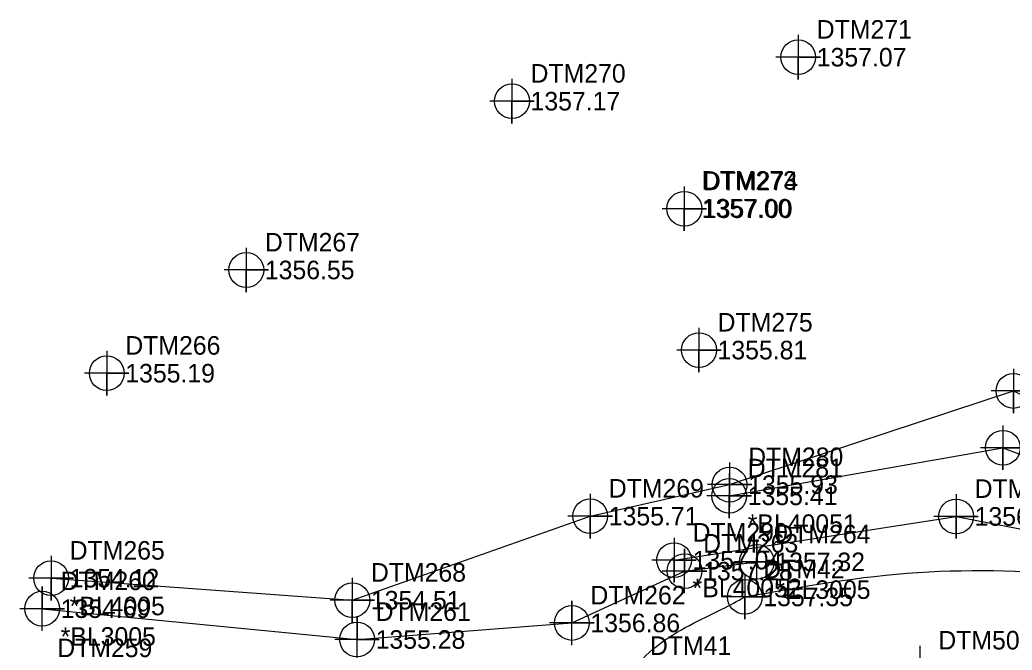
# Model space of a CAD drawing. Extents: x 1251905 to 1252853, y 859795 to 860170.
# Drawn here: x 1251953.9 to 1252087.6, y 860085.2 to 860170.2 of the extents above; entities that cross this region are included whole.
import ezdxf

# ---------------------------------------------------------------- set-up
doc = ezdxf.new("R2010")
doc.units = 0
for name, color, linetype in [('Exist DTM Breakline', 7, 'Continuous'), ('Exist DTM Breakline Cogo Comment', 7, 'Continuous'), ('Exist DTM Breakline Cogo Elevation', 7, 'Continuous'), ('Exist DTM Breakline Cogo Number', 7, 'Continuous'), ('Exist DTM Breakline Cogo Point CELL', 7, 'Continuous'), ('Exist DTM Crownline Cogo Number', 7, 'Continuous'), ('Exist DTM Crownline Cogo Point CELL', 7, 'Continuous'), ('Exist DTM Regular Point CELL', 7, 'Continuous'), ('Exist DTM Regular Point Cogo Elevation', 7, 'Continuous'), ('Exist DTM Regular Point Cogo Number', 7, 'Continuous'), ('Exist Roads EOP', 7, 'Continuous'), ('Exist Roads EOP Cogo Elevation', 7, 'Continuous'), ('Exist Roads EOP Cogo Number', 7, 'Continuous'), ('Exist Roads EOP Cogo Point CELL', 7, 'Continuous'), ('Exist Roads Soil', 7, 'Continuous'), ('Exist Roads Soil Cogo Comment', 7, 'Continuous'), ('Exist Roads Soil Cogo Elevation', 7, 'Continuous'), ('Exist Roads Soil Cogo Number', 7, 'Continuous'), ('Exist Roads Soil Cogo Point CELL', 7, 'Continuous'), ('Exist Vegetation Tree Cogo Elevation', 7, 'Continuous'), ('Exist Vegetation Tree Cogo Number', 7, 'Continuous')]:
    doc.layers.add(name, color=color, linetype=linetype)

msp = doc.modelspace()

# ---------------------------------------------------------------- linework, layer by layer
at = {"layer": 'Exist DTM Breakline'}
for points in [[(1251958.13, 860094.898), (1251998.718, 860091.928), (1252030.771, 860103.262), (1252049.551, 860107.507), (1252087.792, 860120.138), (1252107.828, 860109.909), (1252152.49, 860100.596), (1252183.064, 860094.812), (1252211.515, 860083.799), (1252212.351, 860093.22), (1252191.02, 860107.945), (1252193.563, 860139.71)], [(1252049.493, 860105.996), (1252086.378, 860112.482), (1252107.399, 860104.568), (1252151.324, 860093.395), (1252178.994, 860086.087), (1252207.96, 860079.566), (1252223.738, 860077.321)], [(1252042.065, 860097.328), (1252080.061, 860103.224), (1252106.299, 860098.116), (1252149.813, 860090.533), (1252176.834, 860084.313), (1252221.078, 860071.872)]]:
    msp.add_lwpolyline(points, dxfattribs=at)
at = {"layer": 'Exist DTM Breakline Cogo Point CELL'}
for points in [[(1252087.792, 860123.138), (1252087.792, 860117.138), (1252087.792, 860120.138), (1252090.792, 860120.138), (1252084.792, 860120.138)], [(1252086.378, 860115.482), (1252086.378, 860109.482), (1252086.378, 860112.482), (1252089.378, 860112.482), (1252083.378, 860112.482)], [(1252049.551, 860110.507), (1252049.551, 860104.507), (1252049.551, 860107.507), (1252052.551, 860107.507), (1252046.551, 860107.507)], [(1252049.493, 860108.996), (1252049.493, 860102.996), (1252049.493, 860105.996), (1252052.493, 860105.996), (1252046.493, 860105.996)], [(1252030.771, 860106.262), (1252030.771, 860100.262), (1252030.771, 860103.262), (1252033.771, 860103.262), (1252027.771, 860103.262)], [(1252080.061, 860106.224), (1252080.061, 860100.224), (1252080.061, 860103.224), (1252083.061, 860103.224), (1252077.061, 860103.224)], [(1252042.065, 860100.328), (1252042.065, 860094.328), (1252042.065, 860097.328), (1252045.065, 860097.328), (1252039.065, 860097.328)], [(1251958.13, 860097.898), (1251958.13, 860091.898), (1251958.13, 860094.898), (1251961.13, 860094.898), (1251955.13, 860094.898)], [(1251998.718, 860094.928), (1251998.718, 860088.928), (1251998.718, 860091.928), (1252001.718, 860091.928), (1251995.718, 860091.928)]]:
    msp.add_lwpolyline(points, dxfattribs=at)
for centre in [(1252087.792, 860120.138), (1252086.378, 860112.482), (1252049.551, 860107.507), (1252049.493, 860105.996), (1252030.771, 860103.262), (1252080.061, 860103.224), (1252042.065, 860097.328), (1251958.13, 860094.898), (1251998.718, 860091.928)]:
    msp.add_circle(centre, 2.344, dxfattribs=at)
at = {"layer": 'Exist DTM Crownline Cogo Point CELL'}
msp.add_lwpolyline([(1252075.17, 860085.787), (1252075.17, 860079.787), (1252075.17, 860082.787), (1252078.17, 860082.787), (1252072.17, 860082.787)], dxfattribs=at)
at = {"layer": 'Exist DTM Regular Point CELL'}
for points in [[(1252058.795, 860168.136), (1252058.795, 860162.136), (1252058.795, 860165.136), (1252061.795, 860165.136), (1252055.795, 860165.136)], [(1252020.228, 860162.206), (1252020.228, 860156.206), (1252020.228, 860159.206), (1252023.228, 860159.206), (1252017.228, 860159.206)], [(1252043.449, 860147.707), (1252043.449, 860141.707), (1252043.449, 860144.707), (1252046.449, 860144.707), (1252040.449, 860144.707)], [(1251984.431, 860139.448), (1251984.431, 860133.448), (1251984.431, 860136.448), (1251987.431, 860136.448), (1251981.431, 860136.448)], [(1252045.427, 860128.651), (1252045.427, 860122.651), (1252045.427, 860125.651), (1252048.427, 860125.651), (1252042.427, 860125.651)], [(1251965.627, 860125.531), (1251965.627, 860119.531), (1251965.627, 860122.531), (1251968.627, 860122.531), (1251962.627, 860122.531)]]:
    msp.add_lwpolyline(points, dxfattribs=at)
for centre in [(1252058.795, 860165.136), (1252020.228, 860159.206), (1252043.449, 860144.707), (1251984.431, 860136.448), (1252045.427, 860125.651), (1251965.627, 860122.531)]:
    msp.add_circle(centre, 2.344, dxfattribs=at)
at = {"layer": 'Exist Roads EOP'}
for points in [[(1252051.592, 860092.372), (1252074.929, 860095.679), (1252098.205, 860095.441)], [(1252026.637, 860048.895), (1252028.382, 860064.631), (1252029.451, 860069.227), (1252031.367, 860073.583), (1252033.775, 860077.818), (1252035.053, 860079.927), (1252035.691, 860080.986), (1252036.321, 860082.05), (1252039.681, 860085.702), (1252044.148, 860088.539), (1252048.52, 860090.712), (1252051.592, 860092.372)]]:
    msp.add_spline(points, degree=3, dxfattribs=at)
at = {"layer": 'Exist Roads EOP Cogo Point CELL'}
msp.add_lwpolyline([(1252051.592, 860095.372), (1252051.592, 860089.372), (1252051.592, 860092.372), (1252054.592, 860092.372), (1252048.592, 860092.372)], dxfattribs=at)
msp.add_circle((1252051.592, 860092.372), 2.344, dxfattribs=at)
at = {"layer": 'Exist Roads Soil'}
msp.add_lwpolyline([(1251956.92, 860090.785), (1251999.355, 860086.635), (1252028.297, 860088.86), (1252043.486, 860095.855), (1252053.212, 860097.101)], dxfattribs=at)
at = {"layer": 'Exist Roads Soil Cogo Point CELL'}
for points in [[(1252053.212, 860094.101), (1252053.212, 860100.101), (1252053.212, 860097.101), (1252056.212, 860097.101), (1252050.212, 860097.101)], [(1252043.486, 860092.855), (1252043.486, 860098.855), (1252043.486, 860095.855), (1252046.486, 860095.855), (1252040.486, 860095.855)], [(1251956.92, 860087.785), (1251956.92, 860093.785), (1251956.92, 860090.785), (1251959.92, 860090.785), (1251953.92, 860090.785)], [(1252028.297, 860085.86), (1252028.297, 860091.86), (1252028.297, 860088.86), (1252031.297, 860088.86), (1252025.297, 860088.86)], [(1251999.355, 860083.635), (1251999.355, 860089.635), (1251999.355, 860086.635), (1252002.355, 860086.635), (1251996.355, 860086.635)]]:
    msp.add_lwpolyline(points, dxfattribs=at)
for centre in [(1252053.212, 860097.101), (1252043.486, 860095.855), (1251956.92, 860090.785), (1252028.297, 860088.86), (1251999.355, 860086.635)]:
    msp.add_circle(centre, 2.344, dxfattribs=at)

# ---------------------------------------------------------------- texts
at = {"layer": 'Exist DTM Breakline Cogo Comment'}
for s, p in [('*BL40051', (1252051.993, 860100.996)), ('*BL40052', (1252044.565, 860092.328)), ('*BL4005', (1251960.63, 860089.898))]:
    msp.add_text(s, height=2.5, dxfattribs=at).set_placement(p)
at = {"layer": 'Exist DTM Breakline Cogo Elevation'}
for s, p in [('1355.93', (1252052.051, 860106.257)), ('1355.41', (1252051.993, 860104.746)), ('1355.71', (1252033.271, 860102.012)), ('1356.20', (1252082.561, 860101.974)), ('1357.04', (1252044.565, 860096.078)), ('1354.12', (1251960.63, 860093.648)), ('1354.51', (1252001.218, 860090.678))]:
    msp.add_text(s, height=2.5, dxfattribs=at).set_placement(p)
at = {"layer": 'Exist DTM Breakline Cogo Number'}
for s, p in [('DTM280', (1252052.051, 860110.007)), ('DTM281', (1252051.993, 860108.496)), ('DTM269', (1252033.271, 860105.762)), ('DTM291', (1252082.561, 860105.724)), ('DTM290', (1252044.565, 860099.828)), ('DTM265', (1251960.63, 860097.398)), ('DTM268', (1252001.218, 860094.428))]:
    msp.add_text(s, height=2.5, dxfattribs=at).set_placement(p)
at = {"layer": 'Exist DTM Crownline Cogo Number'}
msp.add_text('DTM50', height=2.5, dxfattribs=at).set_placement((1252077.67, 860085.287))
at = {"layer": 'Exist DTM Regular Point Cogo Elevation'}
for s, p in [('1357.07', (1252061.295, 860163.886)), ('1357.17', (1252022.728, 860157.956)), ('1357.00', (1252045.949, 860143.457)), ('1356.55', (1251986.931, 860135.198)), ('1355.81', (1252047.927, 860124.401)), ('1355.19', (1251968.127, 860121.281))]:
    msp.add_text(s, height=2.5, dxfattribs=at).set_placement(p)
at = {"layer": 'Exist DTM Regular Point Cogo Number'}
for s, p in [('DTM271', (1252061.295, 860167.636)), ('DTM270', (1252022.728, 860161.706)), ('DTM274', (1252045.949, 860147.207)), ('DTM267', (1251986.931, 860138.948)), ('DTM275', (1252047.927, 860128.151)), ('DTM266', (1251968.127, 860125.031))]:
    msp.add_text(s, height=2.5, dxfattribs=at).set_placement(p)
at = {"layer": 'Exist Roads EOP Cogo Elevation'}
msp.add_text('1357.35', height=2.5, dxfattribs=at).set_placement((1252054.092, 860091.122))
at = {"layer": 'Exist Roads EOP Cogo Number'}
for s, p in [('DTM42', (1252054.092, 860094.872)), ('DTM41', (1252038.821, 860084.55))]:
    msp.add_text(s, height=2.5, dxfattribs=at).set_placement(p)
at = {"layer": 'Exist Roads Soil Cogo Comment'}
for s, p in [('*EL3005', (1252055.712, 860092.101)), ('*BL3005', (1251959.42, 860085.785))]:
    msp.add_text(s, height=2.5, dxfattribs=at).set_placement(p)
at = {"layer": 'Exist Roads Soil Cogo Elevation'}
for s, p in [('1357.32', (1252055.712, 860095.851)), ('1357.28', (1252045.986, 860094.605)), ('1354.69', (1251959.42, 860089.535)), ('1356.86', (1252030.797, 860087.61)), ('1355.28', (1252001.855, 860085.385))]:
    msp.add_text(s, height=2.5, dxfattribs=at).set_placement(p)
at = {"layer": 'Exist Roads Soil Cogo Number'}
for s, p in [('DTM264', (1252055.712, 860099.601)), ('DTM263', (1252045.986, 860098.355)), ('DTM260', (1251959.42, 860093.285)), ('DTM262', (1252030.797, 860091.36)), ('DTM261', (1252001.855, 860089.135)), ('DTM259', (1251958.953, 860084.254))]:
    msp.add_text(s, height=2.5, dxfattribs=at).set_placement(p)
at = {"layer": 'Exist Vegetation Tree Cogo Elevation'}
msp.add_text('1357.00', height=2.5, dxfattribs=at).set_placement((1252045.804, 860143.521))
at = {"layer": 'Exist Vegetation Tree Cogo Number'}
msp.add_text('DTM273', height=2.5, dxfattribs=at).set_placement((1252045.804, 860147.271))

doc.saveas('drawing.dxf')
